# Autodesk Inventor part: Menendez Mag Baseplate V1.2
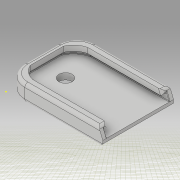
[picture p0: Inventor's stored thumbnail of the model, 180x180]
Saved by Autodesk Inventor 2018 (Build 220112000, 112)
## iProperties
Created: 2019-06
Part Number: Menendez Mag Baseplate V1.2
Material: Generic
Document SubType Name: Modeling
Designer: Ivan
Density: 1 g/cm^3
Appearance: Default
Author: Ivan
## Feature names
1. Extrusion1
2. Fillet1
3. Extrusion2
4. Sweep1
5. Mirror1
6. Extrusion3
7. Chamfer1
8. Extrusion4
9. Mirror2
10. Extrusion5
11. Fillet2
12. Fillet3
13. Extrusion6
## Parameters: d0 = 39.3192 mm, d1 = 28.7782 mm, d2 = 2.54 mm, d3 = 0, d5 = 7.62 mm, d6 = 3.1496 mm, d7 = 3.1496 mm, d9 = 7.62 mm, d10 = 7.62 mm, d11 = 4.064 mm, d12 = 0, d15 = 1.905 mm, d16 = 0, d17 = 0, d18 = 2.54 mm, d19 = 158 deg, d20 = 50.8 mm, d21 = 0, d22 = 1.27 mm, d23 = 3.175 mm, d24 = 45 deg, d25 = 50.8 mm, d26 = 0, d27 = 2.2098 mm, d28 = 9.779 mm, d29 = 4.572 mm, d30 = 25.4 mm, d31 = 0, d32 = 1.27 mm, d33 = 0.2032 mm, d50 = 5.334 mm, d51 = 25.4 mm, d52 = 0
